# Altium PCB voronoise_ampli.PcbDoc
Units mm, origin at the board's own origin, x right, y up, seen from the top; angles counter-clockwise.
Board outline 50 x 50 mm, 2 copper layers (Top Layer, Bottom Layer); 34 components, 24 nets, 114 pads, 26 vias.
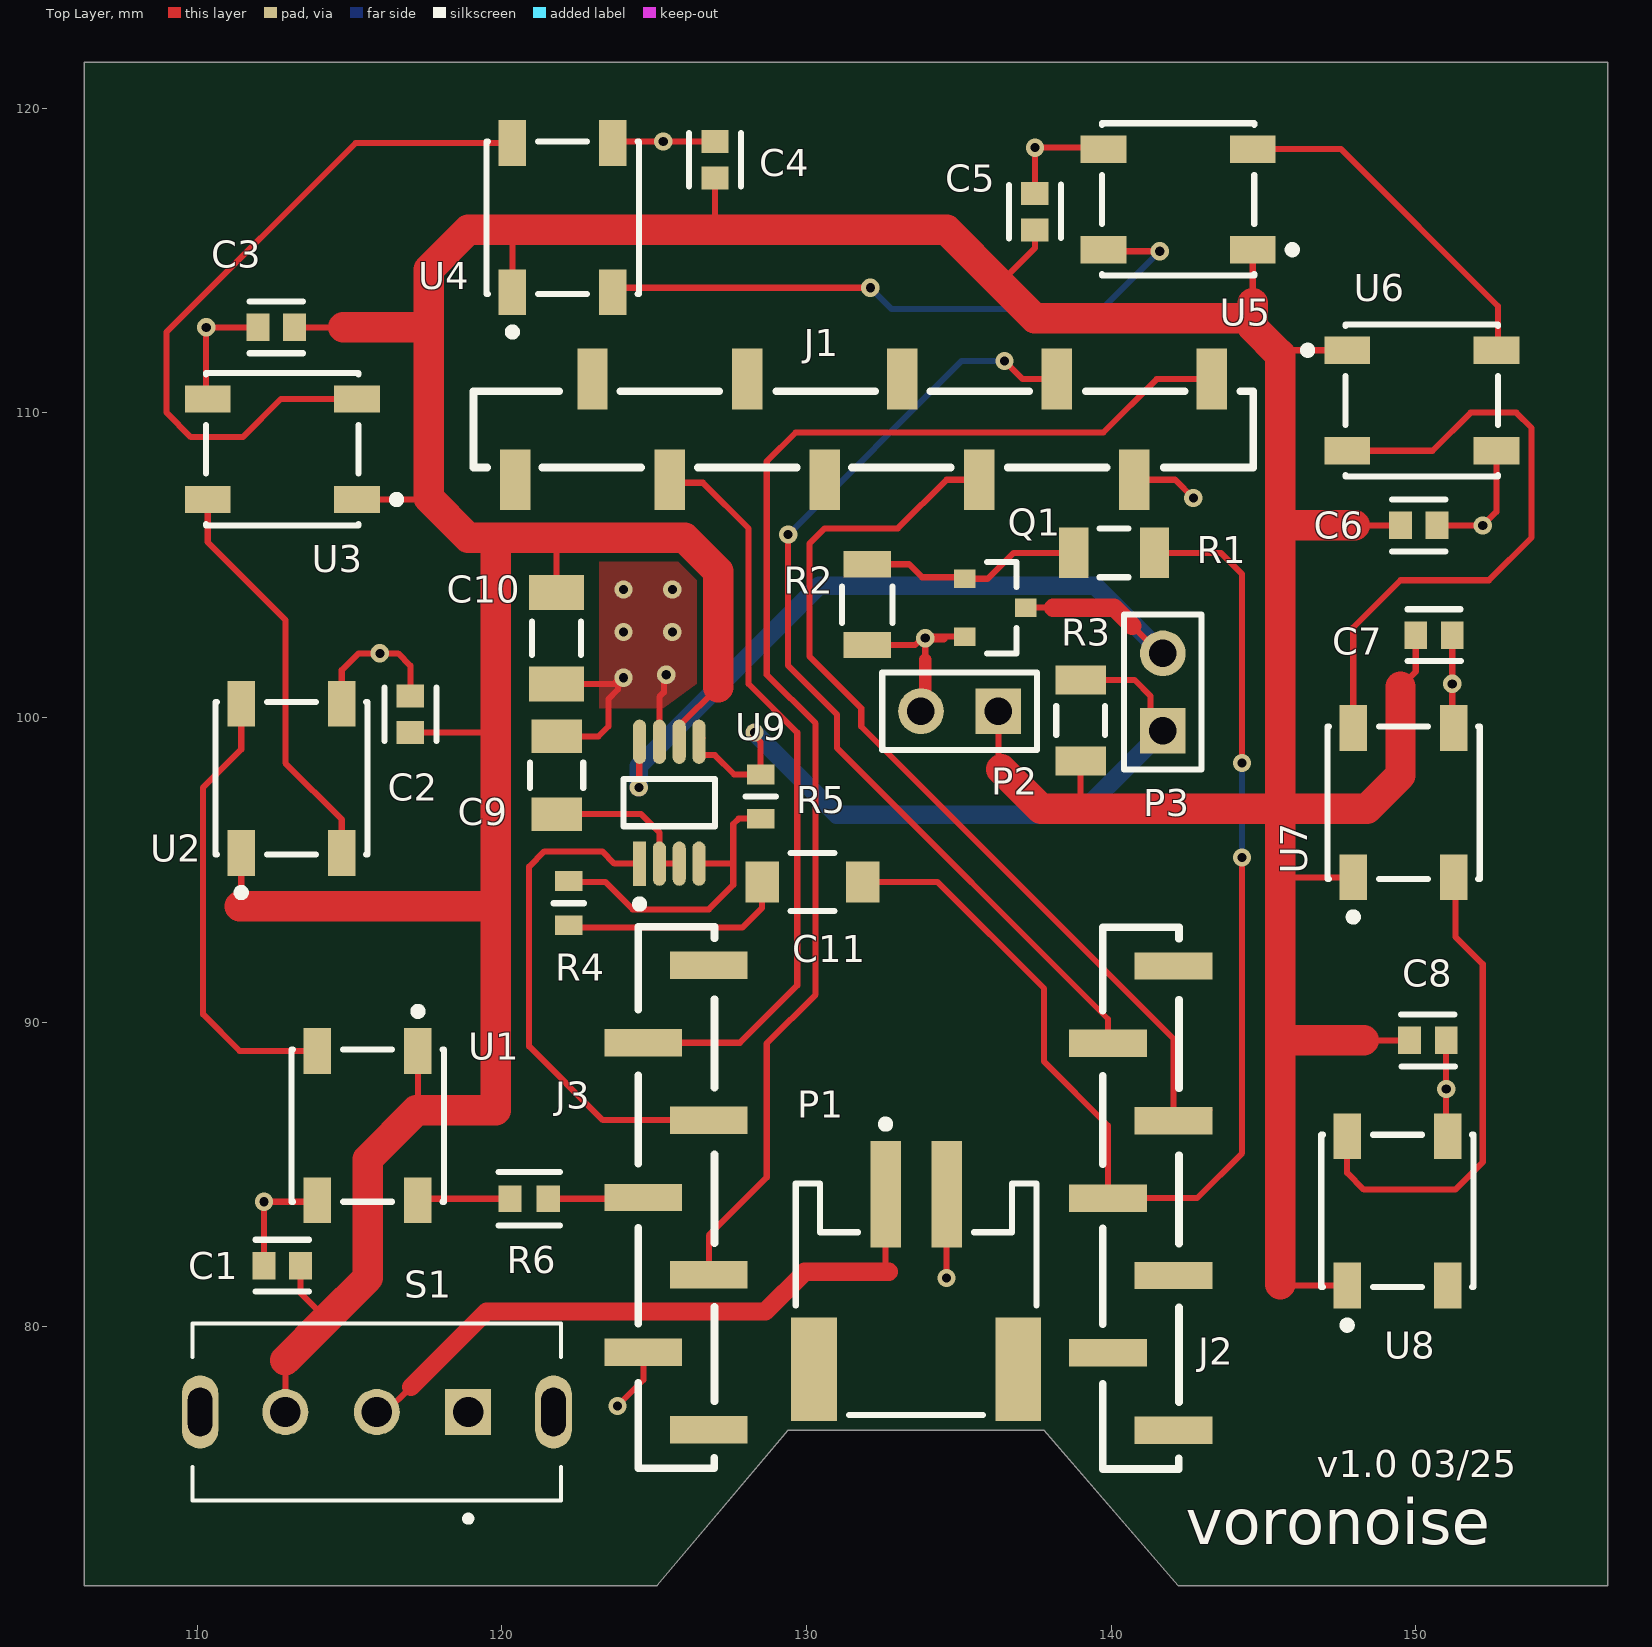
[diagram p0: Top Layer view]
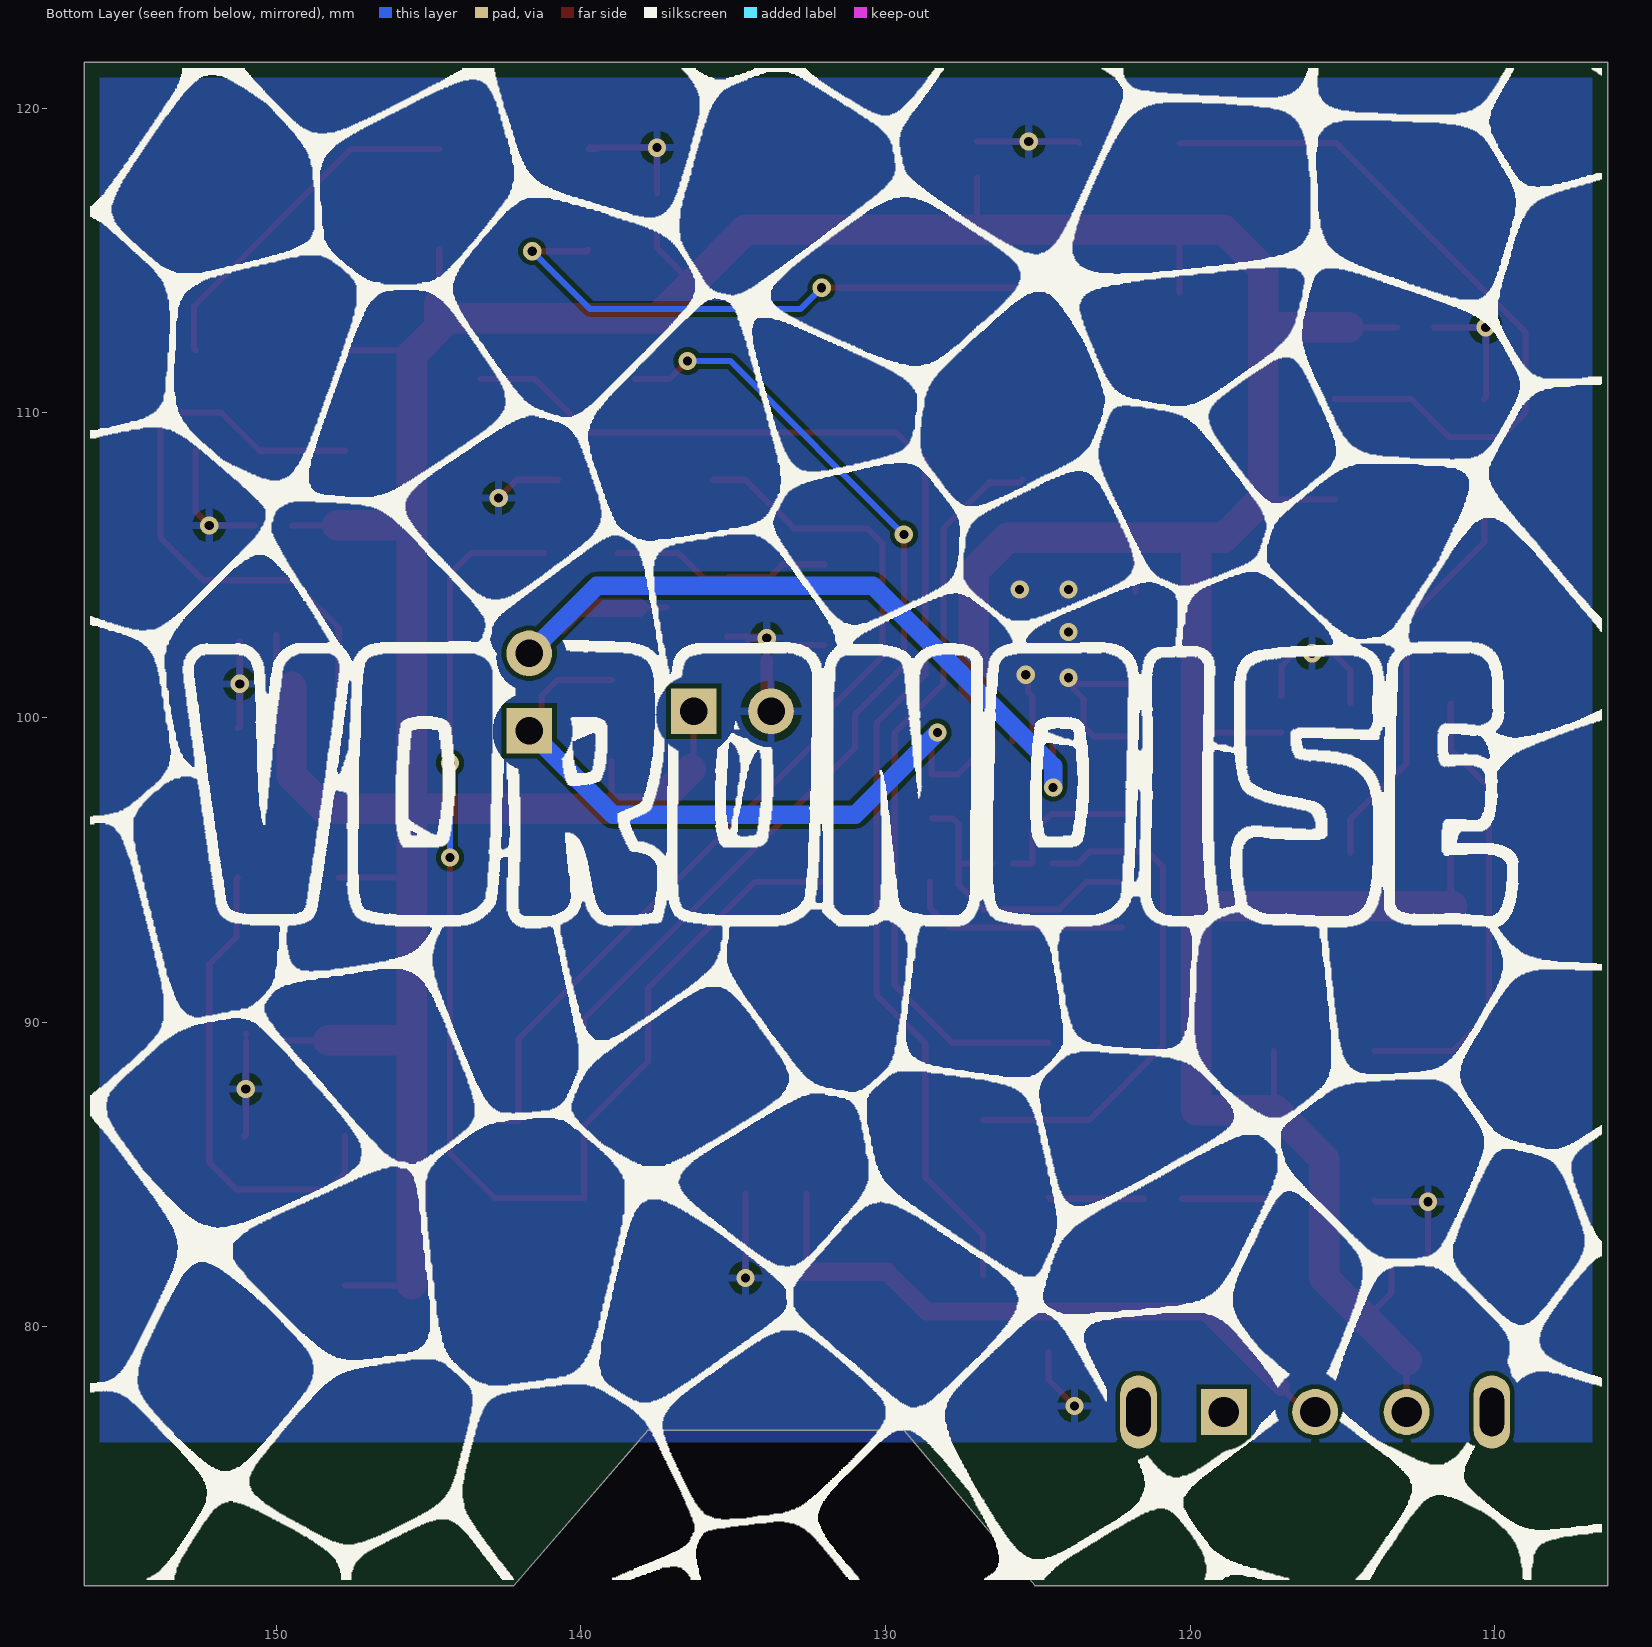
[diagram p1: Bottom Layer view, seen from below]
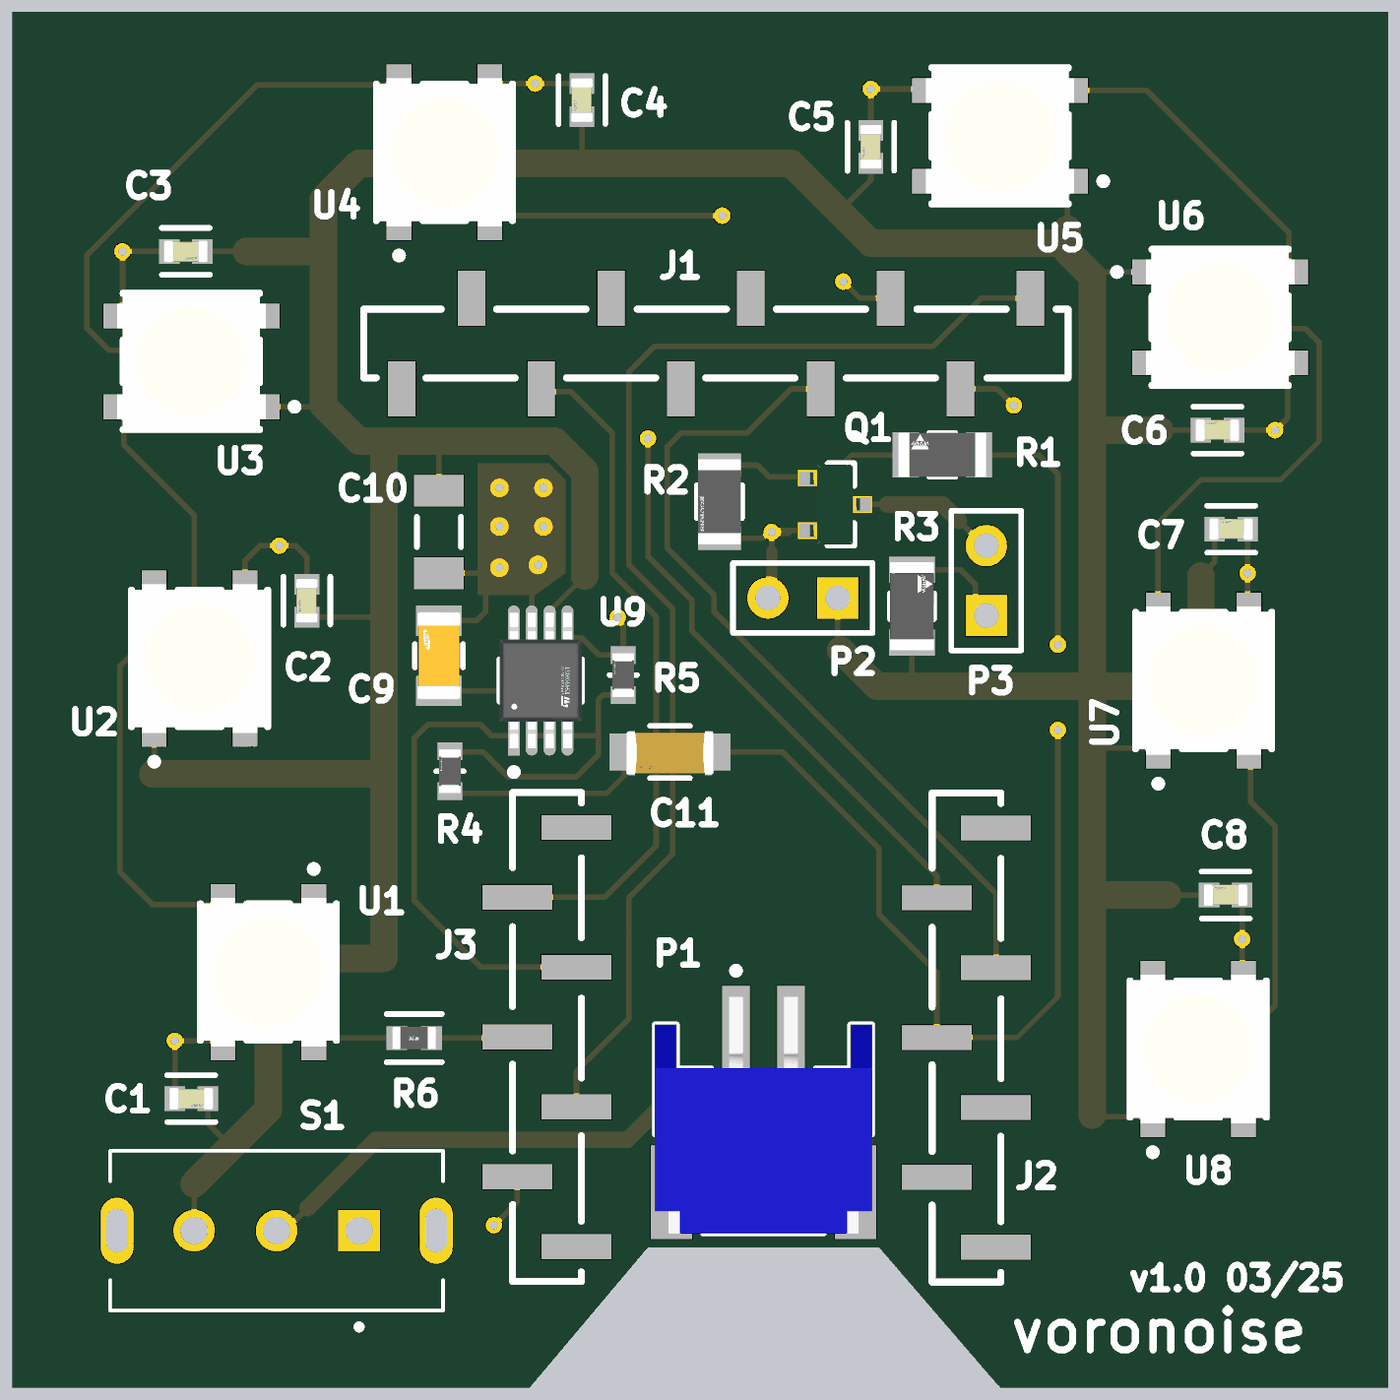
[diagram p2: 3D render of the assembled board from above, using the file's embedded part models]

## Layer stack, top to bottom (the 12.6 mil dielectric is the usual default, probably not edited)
Top Solder: solder mask 0.0102, Solder Resist, Dk 3.5
Top Layer: signal copper 0.0356
Dielectric 1: dielectric 0.32, FR-4, Dk 4.8
Bottom Layer: signal copper 0.0356
Bottom Solder: solder mask 0.0102, Solder Resist, Dk 3.5

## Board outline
106.3,71.5 106.3,121.5 156.3,121.5 156.3,71.5 142.2,71.5 137.8,76.6 129.4,76.6 125.1,71.5

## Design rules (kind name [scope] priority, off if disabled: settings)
AssemblyTestpoint [All] p1: testpointundercomponent=TRUE minsize=1 maxsize=2.5 preferedsize=1.5 minholesize=0 maxholesize=1.016 preferedholesize=0.8 testpointgrid=0.025 usegrid=TRUE gridtolerance=0 allowsidetop=TRUE allowsidebottom=TRUE
Clearance [All] p1: gap=0.15 ignorepadtopadclearanceinfootprint=FALSE except(0.1: Arc-Arc Arc-Track Track-Track; 0.2: Arc-Hole Track-Hole)
FabricationTestpoint [All] p1: side=3 testpointundercomponent=TRUE minsize=1 maxsize=2.54 preferedsize=1.5 minholesize=0 maxholesize=1.016 preferedholesize=0.8 testpointgrid=0.025 allowsidetop=TRUE allowsidebottom=TRUE usegrid=TRUE gridtolerance=0
HoleSize [All] p1: absolutevalues=TRUE maxlimit=6.3 minlimit=0.3 maxpercent=80.000 minpercent=20.000
HoleToHoleClearance [All] p1: gap=0.2 allowstackedmicrovias=TRUE
MinimumSolderMaskSliver [All] p1: minsoldermaskwidth=0.1
PlaneClearance [All] p1: clearance=0.4
PlaneConnect [All] p1: planeconnectstyle=Relief reliefexpansion=0.4 reliefentries=4 reliefconductorwidth=0.25 reliefairgap=0.2
PolygonConnect [All] p1: connectstyle=Relief reliefconductorwidth=0.25 reliefentries=4 polygonreliefangle="90 Angle" airgapwidth=0.25
RoutingVias [All] p1: holewidth=0.3 width=0.6 viastyle="Through Hole" minholewidth=0.2 minwidth=0.5 maxholewidth=0.5 maxwidth=1
SilkToSilkClearance [All] p1: silktosilkclearance=0.2
SilkToSolderMaskClearance [IsPad] p1: minsilkscreentomaskgap=0.05 clearancetoexposedcopper=TRUE
SolderMaskExpansion [All] p1: expansion=0.038 istentingtop=FALSE
SupplyNets "Schematic Supply Nets_2" [InNet('Vccbat')] p1: voltage=0.000
SupplyNets "Schematic Supply Nets_1" [InNet('VCC')] p2: voltage=0.000
SupplyNets "Schematic Supply Nets" [InNet('GND')] p3: voltage=0.000
Width [All] p1: maxlimit=1 minlimit=0.1 preferedwidth=0.2
21 further rules are at their usual default settings.

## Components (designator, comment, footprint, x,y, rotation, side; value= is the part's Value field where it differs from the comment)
C1 "C0603C104K4RACTU" FP-C0603C-CF-MFG 112.8,82 r180 top value="0.10 μF"
C2 "C0603C104K4RACTU" FP-C0603C-CF-MFG 117,100.1 r90 top value="0.10 μF"
C3 "C0603C104K4RACTU" FP-C0603C-CF-MFG 112.6,112.8 r180 top value="0.10 μF"
C4 "C0603C104K4RACTU" FP-C0603C-CF-MFG 127,118.3 r90 top value="0.10 μF"
C5 "C0603C104K4RACTU" FP-C0603C-CF-MFG 137.5,116.6 r90 top value="0.10 μF"
C6 "C0603C104K4RACTU" FP-C0603C-CF-MFG 150.1,106.3 r0 top value="0.10 μF"
C7 "C0603C104K4RACTU" FP-C0603C-CF-MFG 150.6,102.7 r0 top value="0.10 μF"
C8 "C0603C104K4RACTU" FP-C0603C-CF-MFG 150.4,89.4 r0 top value="0.10 μF"
C9 "CL31B105KOFNNNE" FP-CL31-IPC_C 121.8,98.1 r90 top
C10 "CAP 10uF 25V 1206(3216)" CAPC1206(3216)190_N 121.8,102.6 r90 top value=10uF
C11 "CGA5L2X8R1H334K160AA" FP-CGA5L-0_3-0_1-MFG 130.2,94.6 r180 top
J1 "NPTC101KFXC-RC" NPTC101KFXC-RC 140.76,111.1 r270 top
J2 "BL LP 5 SMD 7 Z SM" "BL LP 5 SMD 7 Z SM" 141.28,77.58 r180 top
J3 "BL LP 5 SMD 7 Z SM" "BL LP 5 SMD 7 Z SM" 126.03,77.6 r180 top
P1 "S2B-PH-SM4-TB(LF)(SN)" "JST- S2B-PH-SM4-TB(LF)(SN)-2_V" 133.6,80.9 r0 top
P2 "Pads alim micro" HDR1X2 136.3,100.2 r180 top
P3 "Altavoz" HDR1X2 141.7,99.56 r90 top
Q1 "BC847,215" FP-SOT23-MFG 136.2,103.6 r0 top
R1 "CRCW1206220RJNEA" FP-CRCW1206-e3-IPC_C 140.1,105.4 r180 top
R2 "CR1206-JW-102ELF" FP-CR1206-IPC_C 132,103.7 r270 top
R3 "CRCW12060000Z0EA" FP-CRCW1206-e3-IPC_C 139,99.9 r90 top
R4 "ERA-3AEB203V" FP-ERA3A-MFG 122.2,93.9 r90 top
R5 "ERA-3AEB203V" FP-ERA3A-MFG 128.5,97.4 r90 top
R6 "CRG0603ZR" FP-CRG0603-IPC_C 120.9,84.2 r180 top
S1 "SLW-121586-5A-D" SW_SLW-121586-5A-D 115.9,77.2 r180 top
U1 "1655" ADA-RGB-1655_V 115.6,86.6 r270 top
U2 "1655" ADA-RGB-1655_V 113.1,98 r90 top
U3 "1655" ADA-RGB-1655_V 112.8,108.8 r180 top
U4 "1655" ADA-RGB-1655_V 122,116.4 r90 top
U5 "1655" ADA-RGB-1655_V 142.2,117 r180 top
U6 "1655" ADA-RGB-1655_V 150.2,110.4 r0 top
U7 "1655" ADA-RGB-1655_V 149.6,97.2 r90 top
U8 "1655" ADA-RGB-1655_V 149.4,83.8 r90 top
U9 "TS4990IST" FP-MiniSO-8-IPC_C 125.5,97.2 r90 top

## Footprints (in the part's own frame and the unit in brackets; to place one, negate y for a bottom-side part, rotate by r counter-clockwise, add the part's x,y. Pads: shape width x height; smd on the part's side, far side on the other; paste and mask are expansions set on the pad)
ADA-RGB-1655_V [mm] "SMD, 4-Leads, Body 5x5mm"
  rect 1.5x0.9 smd: 1(-2.45,1.65) 2(-2.45,-1.65) 3(2.45,-1.65) 4(2.45,1.65)
  silkscreen extent -3.87,-2.5 2.5,2.5, body extent -2.7,-2.5 2.7,2.5, height 1.68
"BL LP 5 SMD 7 Z SM" [mm] "Fischer elektronik 7 pin female header. SMD."
  rect 2.55x0.9 smd: 1(-0.77,0.98) 2(1.38,-1.56) 3(-0.77,-4.1) 4(1.38,-6.64) 5(-0.77,-9.18) 6(1.38,-11.72) 7(-0.77,-14.26)
  silkscreen extent -0.95,-15.53 1.55,2.25
CAPC1206(3216)190_N [mm] "Chip Capacitor, Body 3.2x1.6mm, Height 1.9mm, IPC Medium Density"
  rect 1.15x1.8 smd: 1(-1.5,0) 2(1.5,0)
  silkscreen extent -0.55,-0.8 0.55,0.8, body extent -1.7,-0.9 1.7,0.9, height 1.9
FP-C0603C-CF-MFG [mm]
  rect 0.75x0.9 smd paste+0 mask+0: 1(-0.6,0) 2(0.6,0)
  silkscreen extent -0.87,-0.85 0.88,0.85, body extent -1.2,-0.6 1.2,0.6, height 0.25
FP-CGA5L-0_3-0_1-MFG [mm]
  rect 1.1x1.35 smd paste+0 mask+0: 1(-1.65,0) 2(1.65,0)
  silkscreen extent -0.72,-0.95 0.72,0.95, body extent -2.3,-1.05 2.3,1.05, height 0.25
FP-CL31-IPC_C [mm]
  rect 1.105x1.658 smd paste+0 mask+0: 1(-1.276,0) 2(1.276,0)
  silkscreen extent -0.42,-0.87 0.42,0.87, body extent -1.93,-0.97 1.93,0.97, height 0.25
FP-CR1206-IPC_C [mil]
  rect 33.79x61.5 smd paste+0 mask+0: 1(-52.24,0) 2(52.24,0)
  silkscreen extent -24,-32 24,32, body extent -73,-36 73,36, height 10
FP-CRCW1206-e3-IPC_C [mm]
  rect 0.956x1.658 smd paste+0 mask+0: 1(-1.326,0) 2(1.326,0)
  silkscreen extent -0.47,-0.8 0.47,0.8, body extent -1.9,-0.97 1.9,0.97, height 0.25
FP-CRG0603-IPC_C [mm]
  rect 0.758x0.858 smd paste+0 mask+0: 1(-0.627,0) 2(0.627,0)
  silkscreen extent -1.01,-0.87 1.01,0.87, body extent -1.11,-0.58 1.11,0.58, height 0.25
FP-ERA3A-MFG [mm]
  rect 0.65x0.9 smd paste+0 mask+0: 1(-0.725,0) 2(0.725,0)
  silkscreen extent 0,-0.5 0,0.5, body extent -1.15,-0.6 1.15,0.6, height 0.25
FP-MiniSO-8-IPC_C [mm]
  rect 1.454x0.433 smd paste+0 mask+0: 1(-2,0.975)
  rrect100% 1.454x0.433 smd paste+0 mask+0: 2(-2,0.325) 3(-2,-0.325) 4(-2,-0.975) 5(2,-0.975) 6(2,-0.325) 7(2,0.325) 8(2,0.975)
  silkscreen extent -3.45,-1.5 0.77,1.5, body extent -2.83,-1.6 2.83,1.6, height 0.25
FP-SOT23-MFG [mm]
  rect 0.7x0.6 smd paste-1000 mask+0: 1(-1,0.95) 2(-1,-0.95) 3(1,0)
  silkscreen extent -0.28,-1.5 0.7,1.5, body extent -1.5,-1.65 1.5,1.65, height 0.25
HDR1X2 [mm] "Connector; Header; 2 Position"
  rect 1.5x1.5 hole 0.9: 1(0,0)
  round 1.5 hole 0.9: 2(2.54,0)
  silkscreen extent -1.27,-1.27 3.81,1.27
"JST- S2B-PH-SM4-TB(LF)(SN)-2_V" [mm] "SMD, 2-Leads, Body 7.9x7.6mm, Pitch 2mm"
  rect 1x3.5 smd: 1(-1,3.45) 2(1,3.45)
  rect 1.5x3.4 smd: MP1(-3.35,-2.3) MP2(3.35,-2.3)
  silkscreen extent -3.95,-3.8 3.95,5.87, body extent -3.95,-3.8 3.95,4.8, height 5.6
NPTC101KFXC-RC [mm] "Sullins Connector Solutions 10 pin female header. SMD."
  rect 2x1 smd: 1(0,2.54) 2(3.3,0) 3(0,-2.54) 4(3.3,-5.08) 5(0,-7.62) 6(3.3,-10.16) 7(0,-12.7) 8(3.3,-15.24) 9(0,-17.78) 10(3.3,-20.32)
  silkscreen extent 0.4,-21.69 2.9,3.91
SW_SLW-121586-5A-D [mm]
  rect 1.508x1.508 / inner round 1.508 / far side rect 1.508x1.508 hole 1: 1(-3,0)
  round 1.508 hole 1: 2(0,0) 3(3,0)
  oval 1.2x2.4 hole 0.8 slot 1.6 at 90 deg: SH1(-5.8,0) SH2(5.8,0)
  silkscreen extent -6.05,-2.9 6.05,3.6

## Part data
C1 C2 C3 C4 C5 C6 C7 C8: library part CMP-2006-03811-3, "Capacitor; Ceramic; Cap; .100uF; Tol 10%; SMT; Vol-Rtg 16V; X7R; Tape and Reel", Capacitance="0.10 μF", Manufacturer=KEMET, Package=C0603C-CF, Temperature="-55°C to +125°C", Temperature Characteristic=X7R, Temperature Coefficient=30ppm/°C, Temperature Range High=+125°C, Temperature Range Low=-55°C, Tolerance=0.1, Voltage Rating="16 V"
C9: library part CMP-13271-000025-1, "Cap Ceramic 1uF 16V X7R ±10% SMD 1206 +125°C Embossed T/R", Capacitance=1uF, Case Code (Imperial)=1206, Case Code (Metric)=3216, Dielectric=X7R, Max Operating Temperature=125°C, Min Operating Temperature=-55°C, Package Quantity=1, Tolerance=10%, Voltage=16V
C10: library part CMP-1037-04981-1, "CAP 10uF 25V -20% to +80% 1206 (3216 Metric) Thickness 1.9mm SMD", Case-EIA=1206, Case-Metric=3216, Rated Voltage="25 V", Tolerance="-20% to +80%"
C11: library part CMP-08246-001129-1, "Cap Ceramic 330nF 50V X8R 10% Pad SMD 1206 +150°C Automotive T/R", Capacitance=330nF, Case Code (Imperial)=1206, Case Code (Metric)=3216, Dielectric=X8R, Max Operating Temperature=150°C, Min Operating Temperature=-55°C, Package Quantity=1, Ratings=AEC-Q200, Tolerance=10%, Voltage Rating=50V
J1: "Sullins Connector Solutions 10 pin female header. SMD."
J2 J3: "Fischer elektronik 7 pin female header. SMD."
P1: library part CMP-1755-00001-1, "Male Header, Pitch 2 mm, 1 x 2 Position, Height 5.5 mm, -25 to 85 degC, RoHS, Tape and Reel", Colour=Black, Current Rating="3 A", Max Operating Temperature=105degC, Min Operating Temperature=-65degC, Package Quantity=100
P2 P3: library part "Header 2", "Header, 2-Pin"
Q1: library part CMP-14406-000009-1, "TRANS NPN 45V 0.1A SOT23", Ambient Temperature Range High=+150°C, Ambient Temperature Range Low=-65°C, Collector Base Voltage=50V, Collector Emitter Breakdown Voltage=45V, Collector Emitter Saturation Voltage=200mV, Emitter Base Voltage=6V, Manufacturer=Nexperia, Max Collector Current=100mA, Package=SOT23, Power Dissipation=250mW, Temperature="to +150°C"
R1: library part CMP-1014-00058-3, "RES Thick Film, 220Ω, 5%, 0.25W, 200ppm/°C, 1206", Case Code (Imperial)=1206, Case Code (Metric)=3216, Max Operating Temperature=155°C, Max Power Dissipation=250mW, Min Operating Temperature=-55°C, Package Quantity=5000, Resistance=220R, Temperature Coefficient=200ppm/°C, Tolerance=5%, Voltage Rating=200V
R2: library part CMP-07231-001820-1, "Thick Film Chip Resistors 1206 1kΩ 0.25W 5% 200ppm/°C", Case Code (Imperial)=1206, Case Code (Metric)=3216, Max Operating Temperature=155°C, Min Operating Temperature=-55°C, Package Quantity=5000, Power Rating=250mW, Resistance=1kR, Temperature Coefficient=200ppm/°C, Tolerance=5%, Voltage Rating=200V
R3: library part CMP-2003-04857-2, "RES Thick Film, 0Ω, 0.25W, 1206", Case Code (Imperial)=1206, Case Code (Metric)=3216, Max Operating Temperature=155°C, Min Operating Temperature=-55°C, Package Quantity=5000, Power Rating=250mW, Resistance=0mR, Temperature Coefficient=100ppm/°C, Tolerance=1%, Voltage Rating=200V
R4 R5: library part CMP-2000-00946-2, "RES SMD 20K OHM 0.1% 1/10W 0603", Case Code (Imperial)=0603, Case Code (Metric)=1608, Max Operating Temperature=155°C, Max Power Dissipation=100mW, Min Operating Temperature=-55°C, Package Quantity=5000, Resistance=20kR, Resistance Tolerance=0.1%, Resistor Type="Thin Film", Temperature Coefficient=25ppm/°C, Voltage Rating=75V
R6: library part CMP-03211-011415-1, "RES SMD 0 OHM JUMPER 1/10W 0603", Case Code (Imperial)=0603, Case Code (Metric)=1608, Max Operating Temperature=125°C, Max Power Dissipation=100mW, Min Operating Temperature=-55°C, Number of Resistors=1, Package Quantity=5000, Resistance=0mR, Resistor Type="Thick Film", Temperature Coefficient=100ppm/°C, Tolerance=0%, Voltage Rating=50V
S1: Package=None
U1 U2 U3 U4 U5 U6 U7 U8: library part CMP-2000-05026-1, "Intelligent Control LED Integrated Light Source, 3.5 to 5.3 V, -25 to 80 degC, 4-Pin SMD, RoHS, Tape and Reel", Color=Red,Green,Blue(RGB), Manufacturer=Adafruit-Industries-LLC, Package Description="4-Pin Surface Mount Device, Body 5 x 5 mm"
U9: library part CMP-12130-000001-1, "IC AMP AUDIO PWR 1.2W MONO 8MSOP", Manufacturer=STMicroelectronics, Max Junction Temp=+150°C, Max Supply Voltage=5.5V, Min Supply Voltage=2.2V, Nominal Supply Current=3.1-3.7mA, Package=MiniSO-8, Power At Speaker R="1.2W @ 8Ω", Temperature="-40°C to +85°C", Temperature Range High=+85°C, Temperature Range Low=-40°C

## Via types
v1: diameter 0.6, hole 0.3, Top Layer to Bottom Layer, 26 vias

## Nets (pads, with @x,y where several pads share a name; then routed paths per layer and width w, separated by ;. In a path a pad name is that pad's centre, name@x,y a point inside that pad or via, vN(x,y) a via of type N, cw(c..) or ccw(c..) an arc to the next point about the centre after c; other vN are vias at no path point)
GND: C1.2 C2.2 C3.2 C4.2 C5.2 C6.2 C7.2 C8.2 C9.2 C10.1 J1.2 J3.2 P1.2 P2.2 Q1.2 R2.2 U1.3 U2.3 U3.3 U4.3 U5.3 U6.3 U7.3 U8.3 U9.7 | length 51.3
  Top Layer w0.2: U3.3 110.3,110.5 v1(110.3,112.8) C3.2 ; U1.3 113.9,84.1 v1(112.2,84.1) C1.2@112.2,82.1 ; U2.3 114.75,101.55 115.3,102.1 v1(116,102.1) 116.6,102.1 117,101.7 C2.2 ; C9.2 123.176,99.376 123.5,99.7 123.5,100.6 123.817,100.917 123.817,101.009 124,101.192 v1(124,101.3) 123.892,101.3 123.692,101.1 C10.1 ; U4.3 123.7,118.9 v1(125.3,118.9) C4.2 ; v1(123.8,77.4) 124.65,78.25 J3.2 ; U9.7 125.175,100.675 125.323,100.823 125.323,101.323 v1(125.4,101.4) ; R2.2 133.565,102.373 133.792,102.6 v1(133.9,102.6) 133.9,102.1 ; 134.55,102.65 Q1.2 ; v1(134.6,81.6) P1.2 ; C5.2 v1(137.5,118.7) 139.7,118.7 U5.3 U5.3@139.45,118.65 ; J1.2 142.1,107.8 v1(142.7,107.2) ; C6.2 v1(152.2,106.3) 152.65,106.75 U6.3 ; C8.2 v1(151,87.8) 151,86.3 U8.3 ; C7.2@151.2,102.5 151.2,99.7 U7.3 ; C1.2@112.2,82.1 112.1,82 C1.2@112.2,82.1
  Top Layer w0.3: v1(133.9,102.6) 134.5,102.6
  Top Layer w0.4: P2.2 133.9,100.34 133.9,101.9
  other v1: 151.2,101.1 124,102.8 125.6,102.8 124,104.2 125.6,104.2
LEDs: J3.4 R6.1 | length 3.1
  Top Layer w0.2: R6.1 124.61,84.2 J3.4
NetC9_1: C9.1 U9.2 U9.3 | length 4.9
  Top Layer w0.2: C9.1@122.2,96.824 124.576,96.824 125.175,96.225 U9.2 U9.3
NetC11_2: C11.2 R4.1 | length 7.4
  Top Layer w0.2: R4.1@122.25,93.1 127.9,93.1 128.542,93.742 128.542,94.592 C11.2
NetJ1_3: J1.3 J2.6 | length 32.5
  Top Layer w0.2: v1(129.4,106) 129.4,101.7 131,100.1 131,99 139.9,90.1 J2.6 ; v1(136.5,111.7) 137.1,111.1 J1.3
  Bottom Layer w0.2: v1(129.4,106) 135.1,111.7 v1(136.5,111.7)
NetJ1_4: J1.4 J2.5 | length 31.7
  Top Layer w0.2: J1.4 134.6,107.8 133,106.2 130.6,106.2 130.1,105.7 130.1,102 131.8,100.3 131.8,99.7 142.05,89.45 J2.5 142.875,86.76 J2.5@143.225,87.11
NetJ1_8: J1.8 J3.6 | length 24.7
  Top Layer w0.2: J3.6 127.82,89.32 129.7,91.2 129.7,99.5 128.1,101.1 128.1,106.2 126.6,107.7 125.62,107.7 J1.8
NetJ3_5: J3.5 U9.1 | length 16.8
  Top Layer w0.2: U9.1@124.525,95.2 123.7,95.2 123.3,95.6 121.4,95.6 120.9,95.1 120.9,89.2 123.32,86.78 J3.5
NetP1_1: P1.1 S1.2 | length 21.3
  Top Layer w0.2: S1.2 116.2,77.2 117.02,78.02 ; P1.1 132.6,81.9 132.7,81.8
  Top Layer w0.6: 117.02,78.02 119.5,80.5 128.65,80.5 129.95,81.8 132.7,81.8
NetP3_1: P3.1 R3.2 R5.2 U9.5 | length 23.9
  Top Layer w0.2: U9.5@126.583,99.317 126.475,99.209 U9.5 126.475,98.868 126.583,98.76 126.992,98.76 127.627,98.125 R5.2 128.5,99.192 128.3,99.392 v1(128.3,99.5) ; R3.2 140.774,101.226 141.3,100.7 141.3,99.96 P3.1@141.76,99.5
  Bottom Layer w0.6: v1(128.3,99.5) 131,96.8 138.94,96.8 P3.1
NetP3_2: P3.2 Q1.3 U9.8 | length 27.8
  Top Layer w0.2: v1(124.5,97.7) 124.513,97.712 124.513,99.188 U9.8 ; Q1.3 138.1,103.6 ; 140.7,103 P3.2@141.6,102.1
  Top Layer w0.6: 138.1,103.6 140.1,103.6 140.7,103
  Bottom Layer w0.6: v1(124.5,97.7) 124.5,98.407 130.414,104.321 139.479,104.321 P3.2
NetQ1_1: Q1.1 R1.2 R2.1 | length 7.3
  Top Layer w0.2: R2.1 133.373,105.027 133.8,104.6 135.15,104.6 Q1.1 135.95,104.55 136.8,105.4 R1.2
NetR4_2: R4.2 R5.1 U9.4 | length 10
  Top Layer w0.2: R4.2@122.372,94.6 123.4,94.6 124.3,93.7 126.8,93.7 127.6,94.5 127.6,95.2 127.6,96.5 127.775,96.675 R5.1 ; U9.4 127.6,95.2
NetR6_2: R6.2 U1.4 | length 3.1
  Top Layer w0.2: U1.4@117.2,84.1 117.3,84.2 R6.2
NetU1_2: U1.2 U2.4 | length 15
  Top Layer w0.2: U2.4 111.45,98.95 110.2,97.7 110.2,90.25 111.4,89.05 U1.2
NetU2_2: U2.2 U3.4 | length 13.4
  Top Layer w0.2: U3.4 110.35,105.75 112.9,103.2 112.9,98.5 114.75,96.65 U2.2
NetU3_2: U3.2 U4.4 | length 23.7
  Top Layer w0.2: U3.2 112.75,110.45 111.5,109.2 109.8,109.2 109,110 109,112.65 115.2,118.85 U4.4
NetU4_2: U4.2 U5.4 | length 21
  Top Layer w0.2: U4.2 123.8,114.1 v1(132.1,114.1) ; U5.4 139.8,115.3 v1(141.6,115.3)
  Bottom Layer w0.2: v1(132.1,114.1) 132.8,113.4 139.7,113.4 v1(141.6,115.3)
NetU5_2: U5.2 U6.4 | length 11.7
  Top Layer w0.2: U5.2 147.55,118.65 152.7,113.5 152.7,112.1 U6.4
NetU6_2: U6.2 U7.4 | length 20.7
  Top Layer w0.2: U6.2 150.55,108.75 151.8,110 153.3,110 153.8,109.5 153.8,105.9 152.4,104.5 149.5,104.5 147.95,102.95 U7.4
NetU7_2: U7.2 U8.4 | length 16
  Top Layer w0.2: U8.4 147.75,85.05 148.3,84.5 151.3,84.5 152.2,85.4 152.2,91.9 151.3,92.8 151.3,94.7 U7.2
Speaker: C11.1 J2.4 R1.1 | length 42.5
  Top Layer w0.2: C11.1 134.3,94.6 137.8,91.1 137.8,88.7 139.9,86.6 J2.4 142.82,84.22 144.3,85.7 v1(144.3,95.4) ; R1.1@141.215,105.4 R1.1 143.6,105.4 144.3,104.7 v1(144.3,98.5)
  Bottom Layer w0.2: v1(144.3,95.4) v1(144.3,98.5)
VCC: J1.1 J3.3 | length 44.5
  Top Layer w0.2: J3.3 126.8,83 128.7,84.9 128.7,89.3 130.3,90.9 130.3,99.8 128.7,101.4 128.7,108.4 129.65,109.35 139.75,109.35 141.5,111.1 J1.1
Vccbat: C1.1 C2.1 C3.1 C4.1 C5.1 C6.1 C7.1 C8.1 C10.2 P2.1 R3.1 S1.3 U1.1 U2.1 U3.1 U4.1 U5.1 U6.1 U7.1 U8.1 U9.6 | length 189.7
  Top Layer w0.2: 111.4,93.8 111.45,93.85 U2.1 ; S1.3 112.9,78.9 ; C3.1 114.8,112.8 ; C1.1 113.4,81.1 114.25,80.25 ; U3.1 117.55,107.15 117.6,107.2 ; C2.1 119.8,99.5 ; 117.2,87.1 117.25,87.15 U1.1 ; 119.7,94.3 119.8,94.4 ; 120.3,116 120.35,115.95 U4.1 ; C10.2 121.8,105.9 ; U9.6@125.833,99.209 125.833,99.729 127.1,100.996 ; 127,116 C4.1 ; P2.1 136.3,98.4 136.4,98.3 ; 136.35,114.25 137.5,115.4 C5.1 ; 139,97 R3.1 ; 144.65,113.6 U5.1 ; 145.45,111.1 145.55,111 ; 145.55,81.4 145.6,81.35 U8.1 ; 145.55,111.925 145.675,112.05 U6.1 ; 145.551,94.8 145.601,94.75 U7.1 ; 148,106.3 C6.1 ; 148.293,89.4 C8.1 ; 149.5,101 150,101.5 C7.1
  Top Layer w1: 111.4,93.8 119.8,93.8 ; 112.9,78.9 114.25,80.25 115.6,81.6 115.6,85.5 117.2,87.1 119.8,87.1 119.8,93.8 ; 114.8,112.8 117.6,112.8 ; 127.1,100.996 127.1,104.8 126,105.9 121.8,105.9 119.8,105.9 ; 136.4,98.3 137.7,97 139,97 145.551,97 ; 144.65,113.6 144.65,113.1 ; 145.525,111.925 144.65,112.8 144.65,113.1 ; 145.55,81.4 145.55,89.4 ; 145.55,92.6 145.55,89.4 ; 145.55,111 145.55,111.925 ; 145.551,92.6 145.551,94.8 145.551,97 ; 145.551,111 145.551,106.3 ; 148,106.3 145.551,106.3 ; 148.293,89.4 145.55,89.4 ; 149.5,101 149.5,98.1 148.4,97 145.551,97 ; 117.6,112.8 117.6,107.2 118.9,105.9 119.8,105.9 ; 117.6,112.8 117.6,114.7 118.9,116 120.3,116 127,116 130.3,116 134.6,116 136.35,114.25 137.5,113.1 144.65,113.1 ; 119.8,93.8 119.8,94.4 119.8,100.9 119.8,105.9 ; 145.551,97 145.551,106.3
pads on no net: J1.5 J1.6 J1.7 J1.9 J1.10 J2.1 J2.2 J2.3 J2.7 J3.1 J3.7 P1.MP1 P1.MP2 S1.1 S1.SH1 S1.SH2 U8.2

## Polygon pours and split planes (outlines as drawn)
GND on Top Layer "NONET_L-01_P-001" (solid, pour order 1): 126,104.9 125.8,105.1 125.6,105.1 124.5,105.1 123.2,105.1 123.2,100.3 125.3,100.3 126.4,101.1 126.4,104.5
GND on Bottom Layer "GND_L02_P000" (solid, pour order 0): 106.8,76.2 106.8,121 155.8,121 155.8,76.2

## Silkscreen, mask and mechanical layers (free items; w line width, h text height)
Top Overlay:
  text "v1.0 03/25" at 146.754,75.054 h0.89
  text "voronoise" at 142.454,72.854 h1.5
Bottom Overlay:
  drawing of 8 lines, arcs and shapes, not listed
Mechanical 1:
  the board outline again, w0.254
